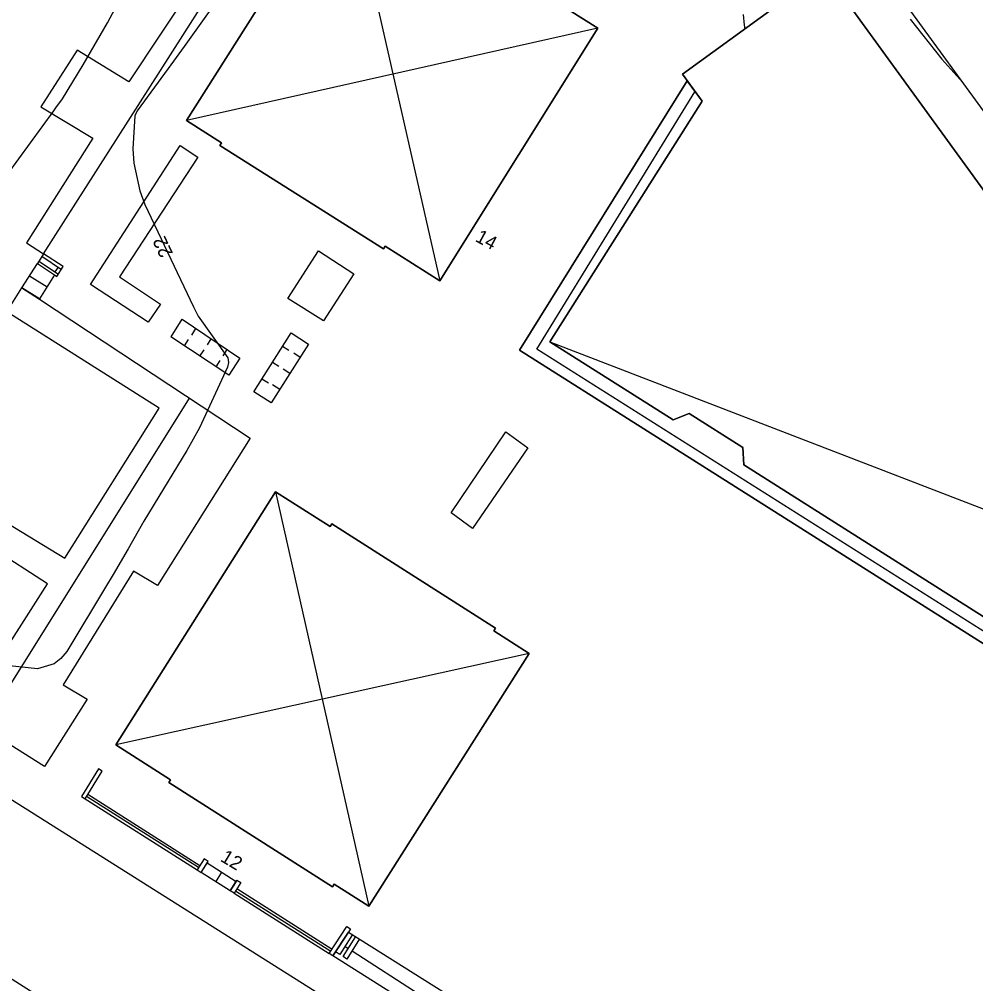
# Model space of a CAD drawing. Extents: x 67169 to 69652, y 20189 to 22818.
# Drawn here: x 69496 to 69565.9, y 21119.5 to 21189.9 of the extents above; entities that cross this region are included whole.
import ezdxf

# ---------------------------------------------------------------- set-up
doc = ezdxf.new("R2010")
doc.units = 0
for name, color, linetype in [('BYGGNAD_HUSLIV', 7, 'Continuous'), ('BYGGNAD_HUSLIV 11', 7, 'Continuous'), ('BYGGNADSDETALJER', 7, 'Continuous'), ('BYGGNADSDETALJER 19', 7, 'Continuous'), ('BYGGNADSSYMBOLER', 7, 'Continuous'), ('BYGGNADSSYMBOLER 30', 7, 'Continuous'), ('HOJDKURVOR_2014', 7, 'Continuous'), ('HOJDKURVOR_TEXTER_2014', 7, 'Continuous'), ('Instruktioner', 7, 'Continuous'), ('MUR_STAKET', 7, 'Continuous'), ('MUR_STAKET_SYMBOL', 7, 'Continuous'), ('Std_Ritningsstämpel', 7, 'Continuous'), ('VAGAR 121', 7, 'Continuous')]:
    doc.layers.add(name, color=color, linetype=linetype)

msp = doc.modelspace()

# ---------------------------------------------------------------- linework, layer by layer
at = {"layer": 'BYGGNAD_HUSLIV'}
for points in [[(69519.896, 21200.89), (69522.446, 21199.273), (69522.569, 21199.467), (69534.403, 21191.965), (69534.281, 21191.771), (69538.276, 21189.239), (69526.74, 21170.81), (69522.741, 21173.337), (69522.618, 21173.143), (69510.682, 21180.688), (69510.805, 21180.882), (69508.253, 21182.496), (69519.896, 21200.89)], [(69544.444, 21185.877), (69554.804, 21193.431), (69589.875, 21145.141), (69579.544, 21137.629), (69577.94, 21140.021), (69577.23, 21139.468), (69548.934, 21157.38), (69548.846, 21158.642), (69544.934, 21161.119), (69543.755, 21160.659), (69534.765, 21166.351), (69545.882, 21183.918), (69544.444, 21185.877)], [(69532.562, 21165.752), (69544.798, 21185.403), (69545.882, 21183.918), (69534.765, 21166.351), (69543.755, 21160.659), (69544.934, 21161.119), (69548.846, 21158.642), (69548.934, 21157.38), (69577.23, 21139.468), (69577.94, 21140.021), (69579.333, 21137.936), (69577.938, 21137.054), (69532.543, 21165.752)], [(69514.739, 21155.42), (69518.728, 21152.878), (69518.852, 21153.072), (69530.801, 21145.457), (69530.677, 21145.263), (69533.257, 21143.63), (69521.552, 21125.188), (69519.023, 21126.799), (69518.899, 21126.605), (69506.949, 21134.215), (69507.074, 21134.415), (69503.085, 21136.957), (69514.739, 21155.42)]]:
    msp.add_lwpolyline(points, dxfattribs=at)
at = {"layer": 'BYGGNAD_HUSLIV 11'}
for points in [[(69519.896, 21200.89), (69522.446, 21199.273), (69522.569, 21199.467), (69534.403, 21191.965), (69534.281, 21191.771), (69538.276, 21189.239), (69526.74, 21170.81), (69522.741, 21173.337), (69522.618, 21173.143), (69510.682, 21180.688), (69510.805, 21180.882), (69508.253, 21182.496), (69519.896, 21200.89)], [(69544.444, 21185.877), (69554.804, 21193.431), (69589.875, 21145.141), (69579.544, 21137.629), (69577.94, 21140.021), (69577.23, 21139.468), (69548.934, 21157.38), (69548.846, 21158.642), (69544.934, 21161.119), (69543.755, 21160.659), (69534.765, 21166.351), (69545.882, 21183.918), (69544.444, 21185.877)], [(69514.739, 21155.42), (69518.728, 21152.878), (69518.852, 21153.072), (69530.801, 21145.457), (69530.677, 21145.263), (69533.257, 21143.63), (69521.552, 21125.188), (69519.023, 21126.799), (69518.899, 21126.605), (69506.949, 21134.215), (69507.074, 21134.415), (69503.085, 21136.957), (69514.739, 21155.42)]]:
    msp.add_lwpolyline(points, dxfattribs=at)
at = {"layer": 'BYGGNADSDETALJER'}
for p, q in [((69497.681, 21172.593), (69499.111, 21171.641)), ((69497.471, 21172.247), (69498.896, 21171.298)), ((69498.87, 21171.801), (69498.645, 21171.465)), ((69519.81, 21122.26), (69520.045, 21122.091))]:
    msp.add_line(p, q, dxfattribs=at)
for points in [[(69497.797, 21172.784), (69497.361, 21172.066), (69498.621, 21171.243), (69498.791, 21171.129), (69499.236, 21171.84), (69497.796, 21172.784)], [(69497.51, 21169.482), (69496.228, 21170.296), (69497.361, 21172.066), (69498.621, 21171.243), (69497.51, 21169.482)], [(69511.866, 21126.997), (69511.435, 21126.314), (69509.317, 21127.654), (69509.757, 21128.341), (69511.866, 21126.997)], [(69532.25, 21113.147), (69518.931, 21121.572), (69520.074, 21123.3), (69533.369, 21114.932), (69532.25, 21113.147)], [(69520.359, 21123.121), (69519.425, 21121.656), (69519.114, 21121.85)], [(69520.88, 21122.793), (69519.955, 21121.315), (69519.673, 21121.503), (69520.601, 21122.967)], [(69520.333, 21121.92), (69525.228, 21118.779), (69525.051, 21118.478), (69532.599, 21113.703)]]:
    msp.add_lwpolyline(points, dxfattribs=at)
at = {"layer": 'BYGGNADSDETALJER 19'}
for p, q in [((69497.681, 21172.593), (69499.111, 21171.641)), ((69497.471, 21172.247), (69498.896, 21171.298)), ((69498.87, 21171.801), (69498.645, 21171.465)), ((69519.81, 21122.26), (69520.045, 21122.091))]:
    msp.add_line(p, q, dxfattribs=at)
for points in [[(69497.797, 21172.784), (69497.361, 21172.066), (69498.621, 21171.243), (69498.791, 21171.129), (69499.236, 21171.84), (69497.796, 21172.784)], [(69497.51, 21169.482), (69496.228, 21170.296), (69497.361, 21172.066), (69498.621, 21171.243), (69497.51, 21169.482)], [(69511.866, 21126.997), (69511.435, 21126.314), (69509.317, 21127.654), (69509.757, 21128.341), (69511.866, 21126.997)], [(69532.25, 21113.147), (69518.931, 21121.572), (69520.074, 21123.3), (69533.369, 21114.932), (69532.25, 21113.147)], [(69520.359, 21123.121), (69519.425, 21121.656), (69519.114, 21121.85)], [(69520.88, 21122.793), (69519.955, 21121.315), (69519.673, 21121.503), (69520.601, 21122.967)], [(69520.333, 21121.92), (69525.228, 21118.779), (69525.051, 21118.478), (69532.599, 21113.703)]]:
    msp.add_lwpolyline(points, dxfattribs=at)
at = {"layer": 'BYGGNADSSYMBOLER'}
for p, q in [((69519.896, 21200.89), (69526.74, 21170.81)), ((69538.276, 21189.239), (69508.253, 21182.496)), ((69496.795, 21171.181), (69498.066, 21170.362)), ((69496.795, 21171.18), (69496.795, 21171.18)), ((69534.765, 21166.351), (69589.875, 21145.141)), ((69514.739, 21155.42), (69521.552, 21125.188)), ((69533.257, 21143.63), (69503.085, 21136.957)), ((69510.811, 21127.669), (69510.376, 21126.984)), ((69510.811, 21127.669), (69510.811, 21127.669))]:
    msp.add_line(p, q, dxfattribs=at)
msp.add_lwpolyline([(69578.662, 21137.523), (69533.822, 21165.808), (69545.358, 21184.602)], dxfattribs=at)
at = {"layer": 'BYGGNADSSYMBOLER 30'}
for p, q in [((69519.896, 21200.89), (69526.74, 21170.81)), ((69538.276, 21189.239), (69508.253, 21182.496)), ((69534.765, 21166.351), (69589.875, 21145.141)), ((69514.739, 21155.42), (69521.552, 21125.188)), ((69533.257, 21143.63), (69503.085, 21136.957))]:
    msp.add_line(p, q, dxfattribs=at)
at = {"layer": 'HOJDKURVOR_2014'}
for points in [[(69510.375, 21191.133), (69508.081, 21187.898), (69506.914, 21186.294), (69504.653, 21183.21), (69504.47, 21182.83), (69504.338, 21180.434), (69504.393, 21179.387), (69504.828, 21177.362), (69505.21, 21176.385), (69508.746, 21168.909), (69509.101, 21168.223), (69511.263, 21165.183), (69511.321, 21164.857), (69511.234, 21164.512), (69509.206, 21160.08), (69508.278, 21158.426), (69506.565, 21155.639), (69505.124, 21153.278), (69503.977, 21151.257), (69502.89, 21149.387), (69502.335, 21148.458), (69499.503, 21143.768), (69499.082, 21143.265), (69498.597, 21142.867), (69497.374, 21142.495), (69495.324, 21142.723)], [(69485.423, 21176.507), (69487.073, 21176.657), (69487.9, 21176.657), (69492.758, 21176.519), (69492.983, 21176.533), (69493.607, 21176.755), (69494.123, 21177.201), (69494.269, 21177.377), (69498.557, 21183.21), (69498.716, 21183.428), (69499.187, 21184.083), (69500.709, 21186.555), (69502.469, 21189.636), (69503.032, 21190.676)], [(69548.877, 21190.239), (69548.955, 21189.467), (69548.987, 21189.19)], [(69561.074, 21189.903), (69563.378, 21186.981), (69564.899, 21185.276)]]:
    msp.add_lwpolyline(points, dxfattribs=at)
at = {"layer": 'MUR_STAKET'}
for p, q in [((69508.913, 21167.331), (69508.61, 21166.849)), ((69508.087, 21166.063), (69508.398, 21166.531)), ((69510.033, 21166.575), (69509.752, 21166.128)), ((69509.219, 21165.319), (69509.527, 21165.781)), ((69511.198, 21165.787), (69510.909, 21165.332)), ((69515.252, 21166.032), (69515.718, 21165.74)), ((69516.546, 21165.223), (69516.07, 21165.539)), ((69510.402, 21164.54), (69510.705, 21164.996)), ((69514.516, 21164.868), (69514.985, 21164.574)), ((69515.796, 21164.04), (69515.298, 21164.37)), ((69513.753, 21163.664), (69514.227, 21163.367)), ((69515.052, 21162.869), (69514.533, 21163.213)), ((69500.574, 21133.185), (69509.017, 21127.844)), ((69509.127, 21128.013), (69500.946, 21133.19)), ((69501.042, 21133.346), (69509.219, 21128.154)), ((69511.722, 21126.133), (69518.666, 21121.739)), ((69511.828, 21126.304), (69518.775, 21121.907)), ((69511.931, 21126.471), (69518.875, 21122.061))]:
    msp.add_line(p, q, dxfattribs=at)
for points in [[(69513.143, 21199.035), (69504.036, 21185.314), (69500.266, 21187.64), (69497.602, 21183.51), (69501.409, 21181.201), (69496.565, 21173.569), (69497.797, 21172.784), (69497.796, 21172.784), (69514.15, 21198.401)], [(69507.771, 21180.667), (69509.066, 21179.837), (69503.348, 21171.106), (69506.355, 21169.114), (69505.458, 21167.779), (69501.232, 21170.546), (69507.772, 21180.666)], [(69517.874, 21172.991), (69520.447, 21171.314), (69518.234, 21167.885), (69515.63, 21169.525), (69517.874, 21172.991)], [(69483.123, 21148.57), (69493.774, 21141.942), (69498.104, 21148.712), (69494.004, 21151.324), (69495.133, 21153.151), (69499.37, 21150.58), (69506.242, 21161.506), (69495.127, 21168.537), (69496.228, 21170.296), (69497.519, 21169.477), (69512.881, 21159.339), (69506.131, 21148.588), (69504.388, 21149.623), (69499.254, 21141.341), (69500.998, 21140.293), (69497.884, 21135.372)], [(69507.114, 21166.729), (69507.929, 21167.997), (69512.137, 21165.152), (69511.335, 21163.926), (69507.102, 21166.711)], [(69515.876, 21167.017), (69517.156, 21166.184), (69514.435, 21161.896), (69513.155, 21162.719), (69515.876, 21167.017)], [(69479.633, 21148.501), (69494.13, 21139.368), (69508.468, 21162.25)], [(69527.553, 21153.89), (69531.548, 21159.79), (69533.154, 21158.634), (69529.132, 21152.748), (69527.553, 21153.891)], [(69500.839, 21133.017), (69502.087, 21135.042), (69501.828, 21135.206), (69500.574, 21133.185)], [(69509.017, 21127.844), (69509.317, 21127.654), (69509.828, 21128.451), (69509.534, 21128.639), (69509.017, 21127.844)], [(69511.722, 21126.133), (69511.435, 21126.314), (69511.923, 21127.087), (69512.202, 21126.908), (69511.722, 21126.133)], [(69518.931, 21121.572), (69518.666, 21121.739), (69519.942, 21123.705), (69520.224, 21123.528), (69520.074, 21123.3), (69518.931, 21121.572)]]:
    msp.add_lwpolyline(points, dxfattribs=at)
at = {"layer": 'MUR_STAKET_SYMBOL'}
for p, q in [((69506.662, 21189.261), (69506.662, 21189.261)), ((69508.192, 21189.064), (69508.192, 21189.064)), ((69505.78, 21187.934), (69505.78, 21187.934)), ((69507.386, 21187.801), (69507.386, 21187.801)), ((69499.712, 21186.787), (69499.712, 21186.787)), ((69501.549, 21186.843), (69501.549, 21186.843)), ((69504.955, 21186.691), (69504.955, 21186.691)), ((69502.779, 21186.084), (69502.779, 21186.084)), ((69506.56, 21186.508), (69506.56, 21186.508)), ((69498.926, 21185.567), (69498.926, 21185.567)), ((69503.923, 21185.378), (69503.923, 21185.378)), ((69504.176, 21185.518), (69504.176, 21185.518)), ((69505.808, 21185.33), (69505.808, 21185.33)), ((69498.077, 21184.253), (69498.077, 21184.253)), ((69505.1, 21184.221), (69505.1, 21184.221)), ((69498.961, 21182.685), (69498.961, 21182.685)), ((69504.294, 21182.958), (69504.294, 21182.958)), ((69500.189, 21181.94), (69500.189, 21181.94)), ((69503.502, 21181.717), (69503.502, 21181.717)), ((69501.281, 21181.278), (69501.281, 21181.278)), ((69501.129, 21180.766), (69501.129, 21180.766)), ((69502.781, 21180.591), (69502.781, 21180.591)), ((69508.409, 21180.252), (69508.409, 21180.252)), ((69500.381, 21179.585), (69500.381, 21179.585)), ((69507.074, 21179.59), (69507.074, 21179.59)), ((69502.018, 21179.392), (69502.018, 21179.392)), ((69499.572, 21178.313), (69499.572, 21178.313)), ((69501.243, 21178.178), (69501.243, 21178.178)), ((69506.257, 21178.327), (69506.257, 21178.327)), ((69507.963, 21178.157), (69507.963, 21178.157)), ((69498.787, 21177.074), (69498.787, 21177.074)), ((69500.437, 21176.915), (69500.437, 21176.915)), ((69505.453, 21177.083), (69505.453, 21177.083)), ((69507.104, 21176.846), (69507.104, 21176.846)), ((69497.962, 21175.774), (69497.962, 21175.774)), ((69499.622, 21175.64), (69499.622, 21175.64)), ((69504.632, 21175.811), (69504.632, 21175.811)), ((69506.284, 21175.595), (69506.284, 21175.595)), ((69497.179, 21174.541), (69497.179, 21174.541)), ((69498.783, 21174.325), (69498.783, 21174.325)), ((69503.827, 21174.566), (69503.827, 21174.566)), ((69505.445, 21174.31), (69505.445, 21174.31)), ((69497.158, 21173.18), (69497.158, 21173.18)), ((69503.04, 21173.347), (69503.04, 21173.347)), ((69504.65, 21173.097), (69504.65, 21173.097)), ((69502.121, 21171.925), (69502.121, 21171.925)), ((69503.813, 21171.817), (69503.813, 21171.817)), ((69517.348, 21172.181), (69517.348, 21172.181)), ((69519.156, 21172.152), (69519.156, 21172.152)), ((69503.407, 21171.064), (69503.407, 21171.064)), ((69516.75, 21171.257), (69516.75, 21171.257)), ((69519.951, 21170.547), (69519.951, 21170.547)), ((69497.148, 21169.692), (69497.148, 21169.692)), ((69501.761, 21170.197), (69501.761, 21170.197)), ((69504.673, 21170.225), (69504.673, 21170.225)), ((69516.132, 21170.302), (69516.132, 21170.302)), ((69503.026, 21169.369), (69503.026, 21169.369)), ((69519.339, 21169.599), (69519.339, 21169.599)), ((69498.473, 21168.815), (69498.473, 21168.815)), ((69504.245, 21168.571), (69504.245, 21168.571)), ((69505.907, 21168.446), (69505.907, 21168.446)), ((69516.931, 21168.703), (69516.931, 21168.703)), ((69518.753, 21168.693), (69518.753, 21168.693)), ((69499.692, 21168.012), (69499.692, 21168.012)), ((69496.691, 21167.52), (69496.691, 21167.52)), ((69500.983, 21167.159), (69500.983, 21167.159)), ((69507.52, 21167.363), (69507.52, 21167.363)), ((69497.977, 21166.707), (69497.977, 21166.707)), ((69502.222, 21166.341), (69502.222, 21166.341)), ((69516.515, 21166.601), (69516.515, 21166.601)), ((69499.228, 21165.916), (69499.228, 21165.916)), ((69503.436, 21165.541), (69503.436, 21165.541)), ((69500.513, 21165.103), (69500.513, 21165.103)), ((69501.787, 21164.298), (69501.787, 21164.298)), ((69504.705, 21164.703), (69504.705, 21164.703)), ((69511.736, 21164.537), (69511.736, 21164.537)), ((69503.038, 21163.507), (69503.038, 21163.507)), ((69505.935, 21163.891), (69505.935, 21163.891)), ((69504.319, 21162.696), (69504.319, 21162.696)), ((69507.183, 21163.068), (69507.183, 21163.068)), ((69513.794, 21162.307), (69513.794, 21162.307)), ((69505.597, 21161.888), (69505.597, 21161.888)), ((69506.242, 21161.49), (69506.242, 21161.49)), ((69509.759, 21161.368), (69509.759, 21161.368)), ((69507.79, 21161.173), (69507.79, 21161.173)), ((69505.414, 21160.161), (69505.414, 21160.161)), ((69507.018, 21159.94), (69507.018, 21159.94)), ((69511.089, 21160.49), (69511.089, 21160.49)), ((69512.312, 21159.684), (69512.312, 21159.684)), ((69532.35, 21159.21), (69532.35, 21159.21)), ((69504.57, 21158.821), (69504.57, 21158.821)), ((69506.206, 21158.646), (69506.206, 21158.646)), ((69530.843, 21158.749), (69530.843, 21158.749)), ((69512.005, 21157.989), (69512.005, 21157.989)), ((69503.796, 21157.589), (69503.796, 21157.589)), ((69505.415, 21157.383), (69505.415, 21157.383)), ((69530.034, 21157.556), (69530.034, 21157.556)), ((69532.49, 21157.663), (69532.49, 21157.663)), ((69511.231, 21156.758), (69511.231, 21156.758)), ((69529.205, 21156.33), (69529.205, 21156.33)), ((69531.672, 21156.466), (69531.672, 21156.466)), ((69502.963, 21156.265), (69502.963, 21156.265)), ((69504.656, 21156.172), (69504.656, 21156.172)), ((69502.161, 21154.99), (69502.161, 21154.99)), ((69510.4, 21155.434), (69510.4, 21155.434)), ((69528.321, 21155.026), (69528.321, 21155.026)), ((69530.854, 21155.269), (69530.854, 21155.269)), ((69503.82, 21154.837), (69503.82, 21154.837)), ((69509.636, 21154.215), (69509.636, 21154.215)), ((69501.378, 21153.745), (69501.378, 21153.745)), ((69503.031, 21153.578), (69503.031, 21153.578)), ((69529.959, 21153.959), (69529.959, 21153.959)), ((69508.804, 21152.89), (69508.804, 21152.89)), ((69528.341, 21153.318), (69528.341, 21153.318)), ((69496.285, 21152.442), (69496.285, 21152.442)), ((69500.517, 21152.377), (69500.517, 21152.377)), ((69502.206, 21152.261), (69502.206, 21152.261)), ((69497.575, 21151.659), (69497.575, 21151.659)), ((69507.966, 21151.558), (69507.966, 21151.558)), ((69498.868, 21150.875), (69498.868, 21150.875)), ((69499.751, 21151.159), (69499.751, 21151.159)), ((69501.414, 21150.997), (69501.414, 21150.997)), ((69507.198, 21150.333), (69507.198, 21150.333)), ((69497.124, 21149.321), (69497.124, 21149.321)), ((69500.62, 21149.73), (69500.62, 21149.73)), ((69504.785, 21149.371), (69504.785, 21149.371)), ((69498.025, 21148.597), (69498.025, 21148.597)), ((69503.925, 21148.863), (69503.925, 21148.863)), ((69506.424, 21149.077), (69506.424, 21149.077)), ((69499.86, 21148.515), (69499.86, 21148.515)), ((69497.248, 21147.381), (69497.248, 21147.381)), ((69499.037, 21147.203), (69499.037, 21147.203)), ((69503.146, 21147.605), (69503.146, 21147.605)), ((69496.464, 21146.155), (69496.464, 21146.155)), ((69498.21, 21145.882), (69498.21, 21145.882)), ((69502.326, 21146.284), (69502.326, 21146.284)), ((69497.449, 21144.667), (69497.449, 21144.667)), ((69501.545, 21145.02), (69501.545, 21145.02)), ((69500.756, 21143.748), (69500.756, 21143.748)), ((69496.64, 21143.377), (69496.64, 21143.377)), ((69499.951, 21142.449), (69499.951, 21142.449)), ((69499.254, 21141.326), (69499.254, 21141.326)), ((69500.125, 21140.817), (69500.125, 21140.817)), ((69500.22, 21139.067), (69500.22, 21139.067)), ((69499.432, 21137.821), (69499.432, 21137.821)), ((69498.631, 21136.558), (69498.631, 21136.558)), ((69505.002, 21130.622), (69505.002, 21130.622)), ((69514.866, 21124.38), (69514.866, 21124.38))]:
    msp.add_line(p, q, dxfattribs=at)
at = {"layer": 'Std_Ritningsstämpel'}
for points in [[(69519.896, 21200.89), (69508.253, 21182.496), (69510.805, 21180.882), (69510.682, 21180.688), (69522.618, 21173.143), (69522.741, 21173.337), (69526.74, 21170.81), (69538.276, 21189.239), (69534.281, 21191.771), (69534.403, 21191.965), (69522.569, 21199.467), (69522.446, 21199.273)], [(69544.444, 21185.877), (69545.882, 21183.918), (69534.765, 21166.351), (69543.755, 21160.659), (69544.934, 21161.119), (69548.846, 21158.642), (69548.934, 21157.38), (69577.23, 21139.468), (69577.94, 21140.021), (69579.544, 21137.629), (69589.875, 21145.141), (69554.804, 21193.431)], [(69544.798, 21185.403), (69532.543, 21165.752), (69577.938, 21137.054), (69579.333, 21137.936), (69577.94, 21140.021), (69577.23, 21139.468), (69548.934, 21157.38), (69548.846, 21158.642), (69544.934, 21161.119), (69543.755, 21160.659), (69534.765, 21166.351), (69545.882, 21183.918)], [(69514.739, 21155.42), (69503.085, 21136.957), (69507.074, 21134.415), (69506.949, 21134.215), (69518.899, 21126.605), (69519.023, 21126.799), (69521.552, 21125.188), (69533.257, 21143.63), (69530.677, 21145.263), (69530.801, 21145.457), (69518.852, 21153.072), (69518.728, 21152.878)]]:
    msp.add_lwpolyline(points, close=True, dxfattribs=at)
at = {"layer": 'VAGAR 121'}
msp.add_line((69497.884, 21135.372), (69479.006, 21147.226), dxfattribs=at)
for points in [[(69531.34, 21231.274), (69599.629, 21137.672), (69602.871, 21140.065), (69603.155, 21140.106), (69603.42, 21140.004), (69603.542, 21139.883)], [(69536.111, 21107.325), (69451.788, 21160.475)], [(69477.62, 21131.253), (69525.068, 21101.057), (69524.03, 21099.312), (69477.932, 21128.61)]]:
    msp.add_lwpolyline(points, dxfattribs=at)

# ---------------------------------------------------------------- texts
at = {"layer": 'HOJDKURVOR_TEXTER_2014'}
msp.add_text('22', height=1, rotation=115.31811, dxfattribs=at).set_placement((69507.278, 21172.808))
at = {"layer": 'Instruktioner'}
for s, rotation, p in [('14', 331.4625, (69529.257, 21173.729)), ('12', 328.98252, (69510.655, 21128.516))]:
    msp.add_text(s, height=1, rotation=rotation, dxfattribs=at).set_placement(p)

doc.saveas('drawing.dxf')
